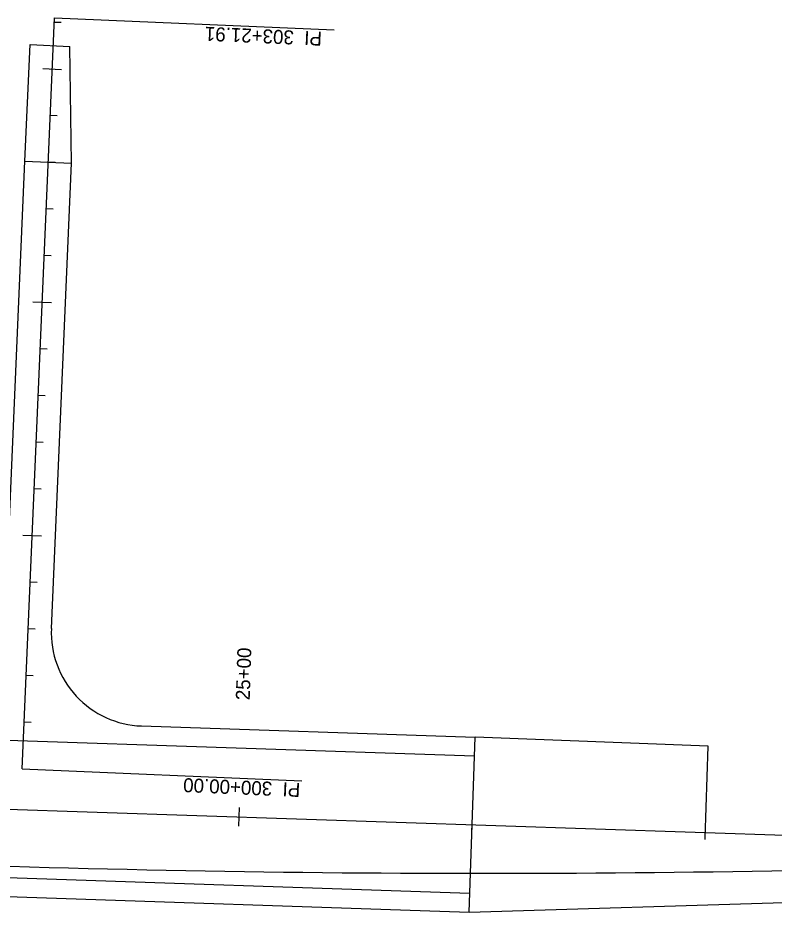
# Model space of a CAD drawing. Extents: x 976639 to 985448, y 1524031 to 1526806.
# Drawn here: x 978354.1 to 978678.1, y 1526423 to 1526806.1 of the extents above; entities that cross this region are included whole.
import ezdxf

# ---------------------------------------------------------------- set-up
doc = ezdxf.new("R2010")
doc.units = 0
for name, color, linetype in [('R_Horiz Alg_Cross Street', 7, 'Continuous'), ('R_Horz Alg', 7, 'Continuous'), ('R_Horz Alg Annot', 7, 'Continuous'), ('R_Horz Alg Annot_Cross Street', 7, 'Continuous'), ('R_Proposed Road_Lane', 7, 'Continuous'), ('R_Proposed Road_Shoulder', 7, 'Continuous'), ('S_WORKING_LINES', 7, 'Continuous')]:
    doc.layers.add(name, color=color, linetype=linetype)

msp = doc.modelspace()

# ---------------------------------------------------------------- linework, layer by layer
at = {"layer": 'R_Horiz Alg_Cross Street'}
msp.add_line((978355.89, 1526484.46), (978369.78, 1526806.07), dxfattribs=at)
at = {"layer": 'R_Horz Alg'}
msp.add_line((976649.79, 1526523.99), (979428.24, 1526431.1), dxfattribs=at)
at = {"layer": 'R_Horz Alg Annot'}
for points in [[(978448.92, 1526467.84), (978448.65, 1526459.85)], [(978548.63, 1526457.51), (978548.73, 1526460.5)], [(978648.57, 1526454.17), (978648.67, 1526457.16)]]:
    msp.add_lwpolyline(points, dxfattribs=at)
at = {"layer": 'R_Horz Alg Annot_Cross Street'}
for points in [[(978369.78, 1526806.07), (978489.67, 1526800.89)], [(978372.69, 1526804.03), (978369.7, 1526804.16)], [(978364.84, 1526784.35), (978372.83, 1526784.01)], [(978370.97, 1526764.07), (978367.97, 1526764.2)], [(978370.11, 1526744.09), (978367.11, 1526744.22)], [(978369.24, 1526724.11), (978366.25, 1526724.24)], [(978368.38, 1526704.13), (978365.38, 1526704.26)], [(978360.52, 1526684.45), (978368.52, 1526684.1)], [(978366.65, 1526664.16), (978363.66, 1526664.29)], [(978365.79, 1526644.18), (978362.79, 1526644.31)], [(978364.93, 1526624.2), (978361.93, 1526624.33)], [(978364.06, 1526604.22), (978361.07, 1526604.35)], [(978356.21, 1526584.54), (978364.2, 1526584.2)], [(978362.34, 1526564.26), (978359.34, 1526564.39)], [(978361.48, 1526544.28), (978358.48, 1526544.41)], [(978360.61, 1526524.29), (978357.62, 1526524.42)], [(978359.75, 1526504.31), (978356.75, 1526504.44)], [(978355.89, 1526484.46), (978475.78, 1526479.28)]]:
    msp.add_lwpolyline(points, dxfattribs=at)
at = {"layer": 'R_Proposed Road_Lane'}
for p, q in [((978357.12, 1526744.65), (978359.4, 1526794.6)), ((978359.4, 1526794.6), (978376.34, 1526793.87)), ((978377.1, 1526743.79), (978376.34, 1526793.87)), ((978348.47, 1526544.35), (978357.12, 1526744.65)), ((978357.12, 1526744.65), (978377.1, 1526743.79)), ((978368.49, 1526544.46), (978377.1, 1526743.79)), ((978129.95, 1526504.02), (978549.71, 1526489.99)), ((978547.48, 1526423.03), (978549.98, 1526497.98)), ((978649.91, 1526494.1), (978549.98, 1526497.98)), ((978648.59, 1526454.7), (978649.91, 1526494.1)), ((978547.74, 1526431.02), (977523.32, 1526465.27))]:
    msp.add_line(p, q, dxfattribs=at)
msp.add_arc((978408.45, 1526542.74), 40, 177.5271, 268.0852, dxfattribs=at)
at = {"layer": 'R_Proposed Road_Shoulder'}
for p, q in [((978407.12, 1526502.76), (978549.98, 1526497.98)), ((977891.17, 1526444.97), (978547.48, 1526423.03)), ((978547.48, 1526423.03), (979108.36, 1526440.24))]:
    msp.add_line(p, q, dxfattribs=at)
at = {"layer": 'S_WORKING_LINES'}
msp.add_line((976649.79, 1526523.99), (979428.24, 1526431.1), dxfattribs=at)
msp.add_arc((978553.83, 1533269.64), 6830, 268.085232, 272.579389, dxfattribs=at)

# ---------------------------------------------------------------- texts
at = {"layer": 'R_Horz Alg Annot'}
msp.add_text('25+00', height=6, rotation=88.0852, dxfattribs=at).set_placement((978453.45, 1526513.72))
at = {"layer": 'R_Horz Alg Annot_Cross Street'}
for s, p in [('PI  303+21.91', (978484.53, 1526800.11)), ('PI  300+00.00', (978475.24, 1526478.31))]:
    msp.add_text(s, height=6, rotation=177.5271, dxfattribs=at).set_placement(p)

doc.saveas('drawing.dxf')
